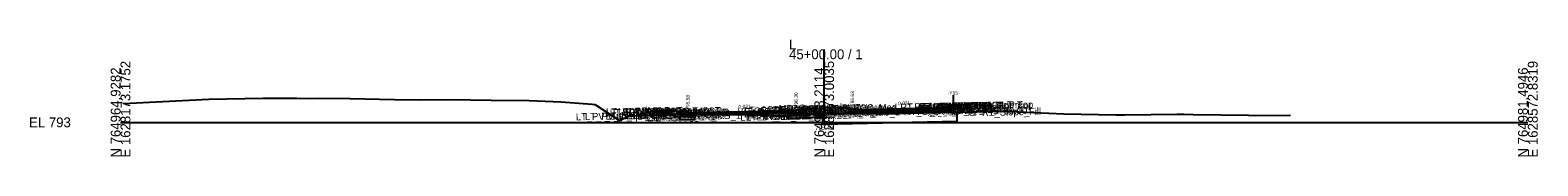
# Model space of a CAD drawing. Extents: x -26 to 4403, y -510 to 9556.
# Drawn here: x 2974.3 to 3402.8, y 4990.3 to 5023.6 of the extents above; entities that cross this region are included whole.
import ezdxf

# ---------------------------------------------------------------- set-up
doc = ezdxf.new("R2010")
doc.units = 0
for name, color, linetype in [('Default', 7, 'Continuous'), ('Exist CMT Pavement', 7, 'Continuous'), ('Exist Cross Section Cell', 7, 'Continuous'), ('Exist XS Center Line Elevation Label', 7, 'Continuous'), ('Exist XS Ground Line', 7, 'Continuous'), ('Prop CMT Conc Surface', 7, 'Continuous'), ('Prop CMT Concrete Structures', 7, 'Continuous'), ('Prop CMT Pvmt Course 1', 7, 'Continuous'), ('Prop CMT Pvmt Course 1 CG', 7, 'Continuous'), ('Prop CMT Pvmt Course 2', 7, 'Continuous'), ('Prop CMT Pvmt Course 2 Wedge', 7, 'Continuous'), ('Prop CMT Pvmt Course 3', 7, 'Continuous'), ('Prop CMT Pvmt Course 3 Wedge', 7, 'Continuous'), ('Prop CMT Pvmt Surface', 7, 'Continuous'), ('Prop CMT Shallow Undercut', 7, 'Continuous'), ('Prop CMT Shallow Undercut Boundary', 7, 'Continuous'), ('Prop CMT Shear Line', 7, 'Continuous'), ('Prop CMT Slope Grass', 7, 'Continuous'), ('Prop CMT Subgrade Earthwork', 7, 'Continuous'), ('Prop CMT Undercut Boundary', 7, 'Continuous'), ('Prop XS Hydro Elevations', 7, 'Continuous'), ('Prop XS SE Text', 7, 'Continuous'), ('Prop XS Side Slope Text', 7, 'Continuous'), ('Scratch_Level_0', 7, 'Continuous')]:
    doc.layers.add(name, color=color, linetype=linetype)

msp = doc.modelspace()

# ---------------------------------------------------------------- linework, layer by layer
at = {"layer": 'Exist CMT Pavement'}
msp.add_lwpolyline([(3163.26, 5002.25), (3170.17, 5002.25), (3178.21, 5002.1), (3182.02, 5002.04), (3187.3, 5001.8), (3189.56, 5001.73)], dxfattribs=at)
at = {"layer": 'Exist Cross Section Cell'}
for p, q in [((3200, 5000), (3200, 5020.75)), ((3000, 5000), (3200, 5000)), ((3200, 5000), (3400, 5000))]:
    msp.add_line(p, q, dxfattribs=at)
at = {"layer": 'Exist XS Ground Line'}
msp.add_lwpolyline([(3000.74, 5005.32), (3004.57, 5005.51), (3025.12, 5006.59), (3040.41, 5006.86), (3041.73, 5006.86), (3050.12, 5006.89), (3053.92, 5006.77), (3056.17, 5006.92), (3065.16, 5006.8), (3077.9, 5006.54), (3085.17, 5006.37), (3093.59, 5006.5), (3105.36, 5006.29), (3116.13, 5006.25), (3125.23, 5005.88), (3134.04, 5005.13), (3134.84, 5005.04), (3135.24, 5004.81), (3141.84, 5000.56), (3144.15, 5001.69), (3144.46, 5001.88), (3157.22, 5002.22), (3158.18, 5002.25), (3160.31, 5002.25), (3170.17, 5002.25), (3178.21, 5002.1), (3182.02, 5002.04), (3187.3, 5001.8), (3189.56, 5001.73), (3190.88, 5001.83), (3192.73, 5002.05), (3193.72, 5002.08), (3196.41, 5002.38), (3199.06, 5002.45), (3200, 5002.48), (3200.61, 5002.49), (3205.15, 5002.52), (3212.12, 5002.52), (3216.67, 5002.48), (3217.48, 5002.48), (3218.59, 5002.48), (3219.64, 5002.48), (3220.48, 5002.48), (3221.08, 5002.57), (3231.84, 5002.83), (3232.87, 5002.84), (3233.29, 5002.84), (3238.27, 5002.94), (3248.47, 5003.14), (3250.53, 5003.16), (3251.07, 5003.14), (3268.07, 5002.45), (3282.92, 5002.11), (3285.44, 5002.13), (3300.36, 5002.29), (3302.18, 5002.31), (3304.87, 5002.27), (3320.57, 5002.02), (3322.66, 5001.93), (3332.49, 5002.05)], dxfattribs=at)
at = {"layer": 'Prop CMT Conc Surface'}
for points in [[(3156.75, 5003.17), (3151.75, 5003.27)], [(3161.25, 5002.58), (3161.25, 5003.08), (3160.75, 5003.08)], [(3163.25, 5002.7), (3161.25, 5002.58)], [(3191.25, 5003.28), (3192, 5003.3), (3192, 5003.46), (3192.76, 5003.71)], [(3208.75, 5003.64), (3208, 5003.63), (3208, 5003.8), (3207.24, 5004.04)]]:
    msp.add_lwpolyline(points, dxfattribs=at)
at = {"layer": 'Prop CMT Concrete Structures'}
for points in [[(3151.75, 5002.93), (3151.75, 5003.27)], [(3151.75, 5003.27), (3156.75, 5003.17)], [(3156.75, 5002.83), (3151.75, 5002.93)], [(3156.75, 5003.17), (3156.75, 5002.83)], [(3163.25, 5002.7), (3161.25, 5002.58), (3161.25, 5003.08), (3160.75, 5003.08)], [(3160.75, 5003.08), (3160.75, 5002.07), (3163.25, 5002.12)], [(3163.25, 5002.12), (3163.25, 5002.7)], [(3191.25, 5003.28), (3192, 5003.3), (3192, 5003.46), (3192.76, 5003.71)], [(3191.25, 5002.7), (3191.25, 5003.28)], [(3192.76, 5002.73), (3191.25, 5002.7)], [(3192.76, 5003.71), (3192.76, 5002.73)], [(3208.75, 5003.64), (3208, 5003.63), (3208, 5003.8), (3207.24, 5004.04)], [(3207.24, 5004.04), (3207.24, 5003.03)], [(3207.24, 5003.03), (3208.75, 5003.06)], [(3208.75, 5003.06), (3208.75, 5003.64)]]:
    msp.add_lwpolyline(points, dxfattribs=at)
at = {"layer": 'Prop CMT Pvmt Course 1'}
for points in [[(3191.25, 5003.28), (3163.25, 5002.7)], [(3163.25, 5002.45), (3189.56, 5003), (3191.25, 5003.03)], [(3163.25, 5002.7), (3163.25, 5002.45), (3163.25, 5002.45)], [(3191.25, 5003.03), (3191.25, 5003.28)], [(3208.75, 5003.64), (3236.75, 5004.22)], [(3236.75, 5003.97), (3208.75, 5003.39)], [(3208.75, 5003.39), (3208.75, 5003.64)], [(3208.75, 5003.39), (3208.75, 5003.39), (3208.75, 5003.39)]]:
    msp.add_lwpolyline(points, dxfattribs=at)
at = {"layer": 'Prop CMT Pvmt Course 1 CG'}
for points in [[(3163.25, 5002.12), (3160.25, 5002.05), (3159.91, 5001.71)], [(3159.91, 5001.71), (3163.25, 5001.78)], [(3163.25, 5001.78), (3163.25, 5002.12)], [(3191.25, 5002.7), (3193.26, 5002.74), (3193.59, 5002.41)], [(3191.25, 5002.36), (3191.25, 5002.7)], [(3193.59, 5002.41), (3191.25, 5002.36)], [(3208.75, 5003.06), (3206.74, 5003.02), (3206.4, 5002.68)], [(3206.4, 5002.68), (3208.75, 5002.73)], [(3208.75, 5002.73), (3208.75, 5003.06)]]:
    msp.add_lwpolyline(points, dxfattribs=at)
at = {"layer": 'Prop CMT Pvmt Course 2'}
for points in [[(3163.25, 5002.12), (3163.25, 5002.12), (3163.25, 5002.45), (3163.25, 5002.45)], [(3163.25, 5002.45), (3163.25, 5002.12)], [(3191.25, 5003.03), (3189.56, 5003)], [(3189.56, 5003), (3189.56, 5002.66)], [(3189.56, 5002.66), (3191.25, 5002.7)], [(3191.25, 5002.7), (3191.25, 5003.03)], [(3208.75, 5003.39), (3236.75, 5003.97)], [(3236.75, 5003.64), (3208.75, 5003.06)], [(3208.75, 5003.06), (3208.75, 5003.39)]]:
    msp.add_lwpolyline(points, dxfattribs=at)
at = {"layer": 'Prop CMT Pvmt Course 2 Wedge'}
for points in [[(3163.25, 5002.45), (3170.17, 5002.59), (3178.21, 5002.76), (3182.02, 5002.84), (3187.3, 5002.95), (3189.56, 5003)], [(3189.56, 5002.66), (3187.3, 5002.62), (3182.02, 5002.51), (3178.21, 5002.43), (3170.17, 5002.26), (3169.44, 5002.25), (3163.25, 5002.25)], [(3163.25, 5002.25), (3163.25, 5002.45)], [(3189.56, 5003), (3189.56, 5002.66)]]:
    msp.add_lwpolyline(points, dxfattribs=at)
at = {"layer": 'Prop CMT Pvmt Course 3'}
for points in [[(3163.25, 5002.12), (3163.25, 5002.12), (3163.25, 5001.78), (3163.25, 5001.78)], [(3163.25, 5001.78), (3163.25, 5002.12)], [(3191.25, 5002.7), (3189.56, 5002.66)], [(3189.56, 5002.66), (3189.56, 5002.33)], [(3189.56, 5002.33), (3191.25, 5002.36)], [(3191.25, 5002.36), (3191.25, 5002.7)], [(3208.75, 5003.06), (3236.75, 5003.64)], [(3236.75, 5003.31), (3208.75, 5002.73)], [(3208.75, 5002.73), (3208.75, 5003.06)]]:
    msp.add_lwpolyline(points, dxfattribs=at)
at = {"layer": 'Prop CMT Pvmt Course 3 Wedge'}
for points in [[(3169.47, 5002.25), (3170.17, 5002.26)], [(3189.56, 5001.73), (3187.3, 5001.8), (3182.02, 5002.04), (3178.21, 5002.1), (3170.17, 5002.25), (3169.47, 5002.25)], [(3170.17, 5002.26), (3178.21, 5002.43), (3182.02, 5002.51), (3187.3, 5002.62), (3189.56, 5002.66)], [(3189.56, 5002.66), (3189.56, 5001.73)]]:
    msp.add_lwpolyline(points, dxfattribs=at)
at = {"layer": 'Prop CMT Pvmt Surface'}
for points in [[(3191.25, 5003.28), (3163.25, 5002.7)], [(3208.75, 5003.64), (3236.75, 5004.22)]]:
    msp.add_lwpolyline(points, dxfattribs=at)
at = {"layer": 'Prop CMT Shallow Undercut'}
for points in [[(3158.91, 5001.7), (3158.91, 5000.7), (3163.25, 5000.78), (3163.25, 5001.78)], [(3189.56, 5001.73), (3189.56, 5001.22), (3199.56, 5001.45), (3199.56, 5002.46), (3198.18, 5002.43), (3196.41, 5002.38), (3193.72, 5002.08), (3192.73, 5002.05), (3190.88, 5001.83)]]:
    msp.add_lwpolyline(points, close=True, dxfattribs=at)
at = {"layer": 'Prop CMT Shallow Undercut Boundary'}
for points in [[(3158.91, 5001.7), (3158.91, 5000.7), (3163.25, 5000.78), (3163.25, 5001.78)], [(3189.56, 5001.73), (3189.56, 5001.22), (3199.56, 5001.45), (3199.56, 5002.46), (3197.84, 5002.42), (3196.41, 5002.38), (3193.72, 5002.08), (3192.73, 5002.05), (3190.88, 5001.83)]]:
    msp.add_lwpolyline(points, close=True, dxfattribs=at)
at = {"layer": 'Prop CMT Shear Line'}
msp.add_line((3236.75, 5002.47), (3236.75, 5007.69), dxfattribs=at)
at = {"layer": 'Prop CMT Slope Grass'}
for points in [[(3160.75, 5003.08), (3151.25, 5003.27), (3147.32, 5001.96)], [(3192.76, 5003.71), (3200, 5004.19)], [(3207.24, 5004.04), (3200, 5004.19)]]:
    msp.add_lwpolyline(points, dxfattribs=at)
at = {"layer": 'Prop CMT Subgrade Earthwork'}
msp.add_line((3236.75, 5003.31), (3236.75, 5002.91), dxfattribs=at)
for points in [[(3163.25, 5001.78), (3159.91, 5001.71), (3158.5, 5003.12)], [(3163.25, 5001.78), (3163.26, 5002.25)], [(3163.25, 5001.78), (3163.25, 5002.12)], [(3163.25, 5001.78), (3163.25, 5001.78)], [(3163.25, 5001.78), (3163.25, 5001.78)], [(3191.25, 5002.36), (3189.56, 5002.33)], [(3189.56, 5002.33), (3189.56, 5001.73)], [(3193.59, 5002.41), (3191.25, 5002.36)], [(3191.25, 5002.36), (3191.25, 5002.36)], [(3195.04, 5003.86), (3193.59, 5002.41)], [(3204.99, 5004.09), (3206.4, 5002.68)], [(3206.4, 5002.68), (3208.75, 5002.73)], [(3208.75, 5002.73), (3236.75, 5003.31)], [(3208.75, 5002.73), (3208.75, 5002.73)], [(3208.75, 5002.73), (3208.75, 5002.73)], [(3236.42, 5003.3), (3236.42, 5003.3)]]:
    msp.add_lwpolyline(points, dxfattribs=at)
at = {"layer": 'Prop CMT Undercut Boundary'}
msp.add_lwpolyline([(3199.56, 5002.46), (3199.56, 4999.45), (3237.75, 5000.33), (3237.75, 5002.93), (3231.84, 5002.83), (3221.08, 5002.57), (3220.48, 5002.48), (3212.12, 5002.52), (3202.43, 5002.5)], close=True, dxfattribs=at)

# ---------------------------------------------------------------- texts
at = {"layer": 'Default'}
msp.add_text('-', height=0.0001, dxfattribs=at).set_placement((3000, 5000))
at = {"layer": 'Exist Cross Section Cell'}
for s, p in [('L', (3190, 5020.75)), ('45+00.00 / 1', (3190, 5017.95)), ('EL 793', (2974, 4998.6))]:
    msp.add_text(s, height=2.8, dxfattribs=at).set_placement(p)
for s, p in [('N 764964.9282', (3000, 4990)), ('E 1628173.1752', (3002.8, 4990)), ('N 764973.2114', (3200, 4990)), ('E 1628373.0035', (3202.8, 4990)), ('N 764981.4946', (3400, 4990)), ('E 1628572.8319', (3402.8, 4990))]:
    msp.add_text(s, height=2.8, rotation=90, dxfattribs=at).set_placement(p)
at = {"layer": 'Exist XS Center Line Elevation Label'}
msp.add_text('795.48', height=1.2, dxfattribs=at).set_placement((3197.48, 4997.88))
at = {"layer": 'Prop XS Hydro Elevations'}
for s, rotation, p in [('795.58', 90, (3161.75, 5003.58)), ('796.30', 90, (3192.5, 5004.3)), ('796.63', 90, (3208.5, 5004.63)), ('-Y15-', 360, (3235.1, 5007.84))]:
    msp.add_text(s, height=1, rotation=rotation, dxfattribs=at).set_placement(p)
at = {"layer": 'Prop XS SE Text'}
for rotation, p in [(1.1885, (3221, 5004.9)), (1.1887, (3175.66, 5003.96))]:
    msp.add_text('0.021', height=1, rotation=rotation, dxfattribs=at).set_placement(p)
at = {"layer": 'Prop XS Side Slope Text'}
msp.add_text('3:1', height=1, rotation=18.429, dxfattribs=at).set_placement((3148.29, 5003.07))
at = {"layer": 'Scratch_Level_0'}
for s, p in [('MD_Crown Point', (3187.09, 5002.93)), ('RT_CG_Top_BOC_Med', (3191.61, 5002.73)), ('RT_Sub_Trench_Out_DLT', (3221.64, 5003.33)), ('RT_CG_Top_Face', (3225.65, 5003.42)), ('RT_CG_Top_Gut', (3226.63, 5002.94)), ('RT_PV1_OEOT', (3227.13, 5003.03)), ('RT_CG_Top_BOC', (3227.18, 5003.44)), ('45+00.00', (3230.44, 5003.07)), ('RT_SDWK_In_Top', (3231.09, 5003.53)), ('RT_SDWK_In_Bot', (3231.12, 5003.2)), ('45+00.00', (3231.6, 5003.29)), ('45+00.00', (3231.94, 5003.54)), ('RT_SDWK_Out_Top', (3234.46, 5003.6)), ('RT_SDWK_Out_Bot', (3234.5, 5003.27)), ('45+00.00', (3235.71, 5003.62)), ('RT_CSLP_Pnt', (3238.9, 5003.68)), ('LT_PV_Sub_Tie_Out', (3129.43, 5000.58)), ('LT_PV_OEEOP_EG', (3132.02, 5000.63)), ('LT_Slope_Fill', (3137.86, 5000.77)), ('LT_SDWK_Out_Top', (3138.01, 5001.99)), ('LT_SDWK_Out_Bot', (3138.04, 5001.66)), ('LT_Sub_Trench_Out_DLT', (3139.09, 5001.73)), ('LT_CSLP_Pnt', (3141.44, 5002.07)), ('LT_SDWK_In_Top', (3144.63, 5001.93)), ('LT_SDWK_In_Bot', (3144.66, 5001.59)), ('LT_CG1_Shelf_Out', (3146.82, 5000.79)), ('LT_CG_Top_Face', (3148.53, 5001.82)), ('LT_CG_Top_BOC', (3149.05, 5001.84)), ('LT_CG_Bot_BOC', (3149.09, 5000.83)), ('LT_Sub_OEOT_CG_1', (3149.49, 5000.51)), ('LT_CG_Top_Gut', (3149.51, 5001.34)), ('LT_Sub_OEOP', (3150.04, 5000.52)), ('45+00.00', (3150.55, 5002.02)), ('LT_Sub_OEEOP', (3152.48, 5000.57)), ('LT_PV2_OEEOP', (3152.58, 5001.24)), ('LT_PV3_OEEOP', (3152.58, 5000.9)), ('LT_CG_Bot_IE', (3153.19, 5000.91)), ('LT_Sub_OEOT', (3153.35, 5000.58)), ('LT_PV2_OEOT', (3153.45, 5001.25)), ('LT_PV3_OEOT', (3153.45, 5000.92)), ('LT_PV1_OEOT', (3154.01, 5001.52)), ('45+00.00', (3155.52, 5001.51)), ('LT_CG_Top_Face_Med', (3175.39, 5002.13)), ('LT_PV_Sub_Tie_In', (3176.15, 5000.46)), ('LT_CG_Top_Gut_Med', (3176.37, 5001.98)), ('LT_CG_Top_BOC_Med', (3177.18, 5002.4)), ('LT_CG_Bot_BOC_Med', (3177.21, 5001.42)), ('LT_CG_Bot_IE_Med', (3177.34, 5001.42)), ('LT_PV_IEEOP_EG', (3177.77, 5000.5)), ('LT_Sub_IEOT_CG_1', (3178.14, 5001.1)), ('LT_Sub_IEEOP', (3179.44, 5001.13)), ('LT_PV2_IEEOP', (3179.54, 5001.8)), ('LT_PV3_IEEOP', (3179.54, 5001.46)), ('LT_CG1_Shelf_In', (3181.46, 5001.5)), ('LT_Sub_PGL', (3182.39, 5001.19)), ('LT_PV2_PGL', (3182.48, 5001.86)), ('LT_PV3_PGL', (3182.48, 5001.52)), ('LT_PV1_PGL', (3183.05, 5002.12)), ('LT_Sub_DLT_In', (3184, 5002.64)), ('LT_Sub_IEOP', (3184.36, 5001.23)), ('45+00.00', (3185.35, 5002.38)), ('45+00.00', (3189.27, 5002.8)), ('RT_CG_Top_Face_Med', (3191.35, 5002.46)), ('RT_CG_Bot_BOC_Med', (3191.64, 5001.72)), ('RT_CG_Top_Gut_Med', (3192.32, 5002.31)), ('RT_Sub_DLT_In', (3193.91, 5002.87)), ('RT_CG_Bot_IE_Med', (3194.79, 5001.78)), ('RT_CG1_Shelf_In', (3194.89, 5001.78)), ('RT_Sub_IEOT_CG_1', (3195.59, 5001.46)), ('RT_Sub_IEOP', (3197.13, 5001.49)), ('RT_Sub_OEEOP', (3197.94, 5001.51)), ('45+00.00', (3198.11, 5002.95)), ('RT_PV2_OEEOP', (3198.03, 5002.18)), ('RT_PV3_OEEOP', (3198.03, 5001.85)), ('45+00.00', (3198.23, 5002.95)), ('RT_Sub_IEEOP', (3198.58, 5001.52)), ('RT_PV2_IEEOP', (3198.68, 5002.19)), ('RT_Sub_PGL', (3199.84, 5001.55)), ('RT_PV2_PGL', (3199.94, 5002.22)), ('RT_PV1_PGL', (3200.5, 5002.48)), ('45+00.00', (3200.79, 5002.79)), ('RT_Sub_OEOT_CG_1', (3222.61, 5002.02)), ('RT_CG1_Shelf_Out', (3225.94, 5002.43)), ('RT_CG_Bot_IE', (3226.3, 5002.43)), ('RT_Sub_OEOT', (3226.47, 5002.1)), ('RT_PV2_OEOT', (3226.56, 5002.77)), ('RT_PV3_OEOT', (3226.56, 5002.44)), ('RT_CG_Bot_BOC', (3227.21, 5002.45)), ('RT_Sub_OEOP', (3229.83, 5002.17)), ('RT_Slope_Fill', (3244.86, 5001.81)), ('45+00.00', (3246.52, 5002.21))]:
    msp.add_text(s, height=2, rotation=1.1458, dxfattribs=at).set_placement(p)

doc.saveas('drawing.dxf')
